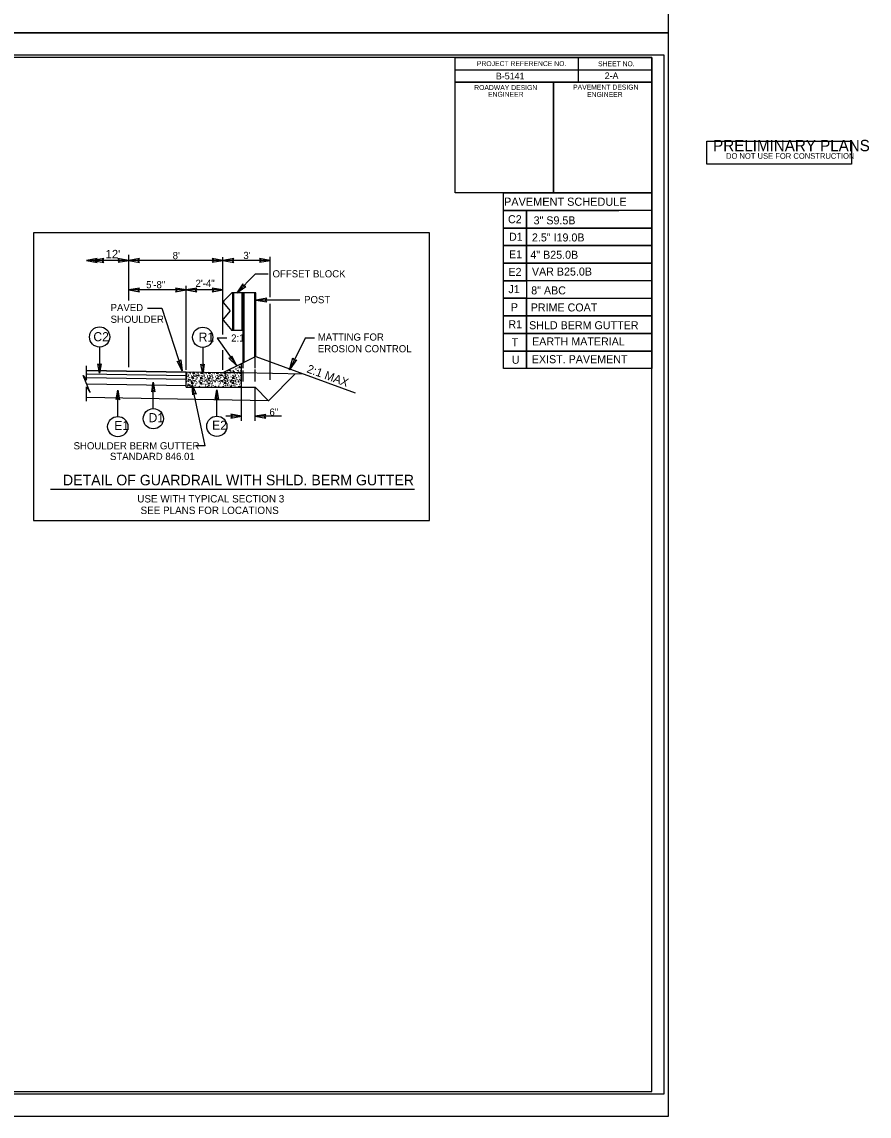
# Model space of a CAD drawing. Extents: x 9470 to 10081, y 10104 to 10463.
# Drawn here: x 9960.6 to 10081.1, y 10104 to 10259.6 of the extents above; entities that cross this region are included whole.
import ezdxf

# ---------------------------------------------------------------- set-up
doc = ezdxf.new("R2010")
doc.units = 0
for name, color, linetype in [('Old_Level_1', 7, 'Continuous'), ('Old_Level_11', 7, 'Continuous'), ('Old_Level_2', 7, 'Continuous'), ('Old_Level_21', 7, 'Continuous'), ('Old_Level_3', 7, 'Continuous'), ('Sheet Cutting Line CELL', 7, 'Continuous'), ('Sheet Data Field CELL', 7, 'Continuous'), ('Sheet Plot Border Inside CELL', 7, 'Continuous'), ('Sheet Plot Border Outside CELL', 7, 'Continuous'), ('Sheet Sticker Preliminary CELL', 7, 'Continuous'), ('Sheet Typical CELL', 7, 'Continuous'), ('Typical ID Circle CELL', 7, 'Continuous'), ('Typical Terminator CELL', 7, 'Continuous'), ('Typical Text ID Circle CELL', 7, 'Continuous')]:
    doc.layers.add(name, color=color, linetype=linetype)

msp = doc.modelspace()

# ---------------------------------------------------------------- linework, layer by layer
at = {"layer": 'Old_Level_1'}
for p, q in [((10050.22, 10235.23), (10050.22, 10210.27)), ((10050.22, 10232.75), (10050.22, 10230.25)), ((9975.8, 10219.94), (9975.8, 10226.43)), ((9989.19, 10215.13), (9989.19, 10226.11)), ((9995.92, 10220.42), (9995.92, 10226.15)), ((9975.8, 10225.63), (9969.78, 10225.63)), ((9989.19, 10225.63), (9975.8, 10225.63)), ((9995.92, 10225.63), (9989.19, 10225.63)), ((9993.79, 10223.68), (9991.15, 10221.03)), ((9995.61, 10223.68), (9993.79, 10223.68)), ((9983.96, 10221.45), (9975.8, 10221.45)), ((9983.96, 10210.08), (9983.96, 10222.01)), ((9989.19, 10221.45), (9983.96, 10221.45)), ((9989.29, 10219.63), (9990.18, 10218.54)), ((9989.3, 10219.9), (9990.46, 10221.03)), ((9993.89, 10221.03), (9990.46, 10221.03)), ((9990.58, 10215.68), (9990.58, 10221.03)), ((9990.73, 10215.68), (9990.73, 10221.03)), ((9991.91, 10215.68), (9991.91, 10221.03)), ((9992.07, 10211.08), (9992.07, 10221.03)), ((9992.22, 10211.15), (9992.22, 10221.03)), ((9993.74, 10211.89), (9993.74, 10221.03)), ((9993.89, 10211.97), (9993.89, 10221.03)), ((10000.15, 10220.01), (9993.89, 10220.01)), ((9995.92, 10208.68), (9995.92, 10219.49)), ((9978.48, 10218.86), (9980.51, 10218.86)), ((9980.51, 10218.86), (9983.4, 10209.96)), ((9990.19, 10218.44), (9989.27, 10217.32)), ((9989.27, 10217.08), (9990.46, 10215.68)), ((9975.8, 10210.48), (9975.8, 10216.22)), ((9992.07, 10215.68), (9990.46, 10215.68)), ((9989.75, 10214.57), (9988.37, 10214.57)), ((9988.37, 10214.57), (9991.15, 10210.64)), ((10002.24, 10214.6), (10000.9, 10214.6)), ((9989.19, 10210.08), (9989.19, 10212.87)), ((9993.89, 10211.97), (9992.07, 10211.08)), ((9993.76, 10210.3), (9993.76, 10211.79)), ((9993.89, 10211.97), (10008, 10206.81)), ((9993.89, 10211.95), (9993.89, 10211.97)), ((9992.07, 10211.08), (9989.19, 10209.68)), ((9990.66, 10210.3), (9990.55, 10210.34)), ((9990.69, 10210.41), (9990.66, 10210.3)), ((9991.84, 10207.62), (9991.84, 10210.97)), ((9992.07, 10210.3), (9992.07, 10211.08)), ((9983.95, 10208.69), (9969.77, 10208.93)), ((9983.96, 10209.77), (9969.78, 10210)), ((9983.96, 10209.25), (9969.88, 10209.48)), ((9983.96, 10207.62), (9983.96, 10209.77)), ((9989.19, 10209.68), (9983.96, 10209.77)), ((9984.09, 10209.55), (9983.96, 10209.76)), ((9983.96, 10209.07), (9983.96, 10209.76)), ((9983.96, 10209.58), (9984.09, 10209.55)), ((9984.91, 10209.08), (9984.72, 10208.93)), ((9984.72, 10208.93), (9985.04, 10208.85)), ((9985.04, 10209.75), (9984.87, 10209.63)), ((9984.87, 10209.63), (9985.2, 10209.55)), ((9985.04, 10208.85), (9984.91, 10209.08)), ((9985.2, 10209.55), (9985.08, 10209.75)), ((9986.16, 10209.03), (9985.96, 10208.88)), ((9985.96, 10208.88), (9986.28, 10208.8)), ((9986.13, 10209.73), (9985.99, 10209.63)), ((9985.99, 10209.63), (9986.31, 10209.55)), ((9986.28, 10208.8), (9986.16, 10209.03)), ((9986.31, 10209.55), (9986.21, 10209.73)), ((9987.22, 10209.71), (9987.1, 10209.63)), ((9987.1, 10209.63), (9987.42, 10209.55)), ((9987.42, 10209.55), (9987.33, 10209.71)), ((9988.3, 10209.69), (9988.22, 10209.63)), ((9988.22, 10209.63), (9988.54, 10209.55)), ((9988.54, 10209.55), (9988.46, 10209.69)), ((9991.84, 10209.64), (9989.19, 10209.68)), ((9989.53, 10209.77), (9989.33, 10209.63)), ((9989.33, 10209.63), (9989.65, 10209.55)), ((9989.59, 10209.05), (9989.39, 10208.91)), ((9989.39, 10208.91), (9989.72, 10208.83)), ((9989.65, 10209.55), (9989.53, 10209.77)), ((9989.72, 10208.83), (9989.59, 10209.05)), ((9990.71, 10209.06), (9990.51, 10208.92)), ((9990.51, 10208.92), (9990.83, 10208.85)), ((9990.77, 10209.84), (9990.57, 10209.69)), ((9990.57, 10209.69), (9990.89, 10209.61)), ((9990.83, 10208.85), (9990.71, 10209.06)), ((9990.89, 10209.61), (9990.77, 10209.84)), ((9991.76, 10209.77), (9991.55, 10209.63)), ((9991.55, 10209.63), (9991.84, 10209.56)), ((9991.84, 10209.63), (9991.76, 10209.77)), ((10000.67, 10209.49), (9991.84, 10209.64)), ((9992.07, 10208.42), (9992.07, 10210)), ((9993.76, 10208.41), (9993.76, 10210.12)), ((9995.67, 10205.7), (9999.48, 10209.51)), ((9983.96, 10207.83), (9969.87, 10208.06)), ((9983.96, 10207.62), (9991.84, 10207.62)), ((9984.87, 10208.34), (9984.67, 10208.2)), ((9984.67, 10208.2), (9984.99, 10208.12)), ((9986.68, 10199.28), (9984.83, 10207.94)), ((9984.99, 10208.12), (9984.87, 10208.34)), ((9986.11, 10208.29), (9985.91, 10208.15)), ((9985.91, 10208.15), (9986.23, 10208.07)), ((9986.23, 10208.07), (9986.11, 10208.29)), ((9989.55, 10208.32), (9989.35, 10208.18)), ((9989.35, 10208.18), (9989.67, 10208.09)), ((9989.67, 10208.09), (9989.55, 10208.32)), ((9990.66, 10208.33), (9990.46, 10208.19)), ((9990.46, 10208.19), (9990.78, 10208.11)), ((9990.78, 10208.11), (9990.66, 10208.33)), ((9991.84, 10202.83), (9991.84, 10207.62)), ((9991.84, 10207.62), (9993.76, 10207.62)), ((9993.76, 10207.62), (9995.67, 10205.7)), ((9993.76, 10202.83), (9993.76, 10207.62)), ((9995.67, 10205.7), (9969.77, 10206.13)), ((9991.84, 10203.49), (9989.62, 10203.49)), ((9997.5, 10203.49), (9993.76, 10203.49)), ((9986.68, 10199.28), (9985.34, 10199.28))]:
    msp.add_line(p, q, dxfattribs=at)
for points in [[(10050.22, 10232.75), (10029.09, 10232.75), (10029.09, 10235.23), (10050.22, 10235.23)], [(10050.22, 10230.25), (10032.4, 10230.25), (10032.4, 10232.75), (10045.53, 10232.75)], [(10000.9, 10214.6), (9998.64, 10210.08)], [(9969.77, 10205.64), (9969.77, 10207.69), (9970.3, 10206.87), (9969.29, 10209.28), (9969.77, 10208.64), (9969.78, 10210.65)]]:
    msp.add_lwpolyline(points, dxfattribs=at)
for points in [[(10029.09, 10232.75), (10032.4, 10232.75), (10032.4, 10230.25), (10029.09, 10230.25)], [(9962.25, 10188.65), (10018.59, 10188.65), (10018.59, 10229.57), (9962.25, 10229.57)], [(10029.09, 10230.25), (10032.4, 10230.25), (10032.4, 10227.76), (10029.09, 10227.76)], [(10032.4, 10230.25), (10050.22, 10230.25), (10050.22, 10227.76), (10032.4, 10227.76)], [(10029.09, 10227.76), (10032.4, 10227.76), (10032.4, 10225.26), (10029.09, 10225.26)], [(10032.4, 10227.76), (10050.22, 10227.76), (10050.22, 10225.26), (10032.4, 10225.26)], [(10029.09, 10225.26), (10032.4, 10225.26), (10032.4, 10222.76), (10029.09, 10222.76)], [(10032.4, 10225.26), (10050.22, 10225.26), (10050.22, 10222.76), (10032.4, 10222.76)], [(10029.09, 10222.76), (10032.4, 10222.76), (10032.4, 10220.26), (10029.09, 10220.26)], [(10029.09, 10220.26), (10032.4, 10220.26), (10032.4, 10217.76), (10029.09, 10217.76)], [(10032.4, 10220.26), (10050.22, 10220.26), (10050.22, 10217.76), (10032.4, 10217.76)], [(10029.09, 10217.76), (10032.4, 10217.76), (10032.4, 10215.26), (10029.09, 10215.26)], [(10032.4, 10217.76), (10050.22, 10217.76), (10050.22, 10215.26), (10032.4, 10215.26)], [(10029.09, 10215.26), (10032.4, 10215.26), (10032.4, 10212.76), (10029.09, 10212.76)], [(10032.4, 10215.26), (10050.22, 10215.26), (10050.22, 10212.76), (10032.4, 10212.76)], [(10029.09, 10212.76), (10032.4, 10212.76), (10032.4, 10210.27), (10029.09, 10210.27)], [(10032.4, 10212.76), (10050.22, 10212.76), (10050.22, 10210.27), (10032.4, 10210.27)], [(9991.52, 10210.4), (9991.82, 10210.49), (9991.78, 10210.3)], [(9969.79, 10210), (9983.96, 10209.77), (9983.95, 10208.69), (9969.77, 10208.93)], [(9984.23, 10208.65), (9984.53, 10208.73), (9984.49, 10208.55)], [(9985.48, 10209.3), (9985.78, 10209.38), (9985.75, 10209.2)], [(9987.06, 10208.9), (9987.36, 10208.99), (9987.33, 10208.81)], [(9988.29, 10208.85), (9988.49, 10208.98), (9988.61, 10208.76)], [(9988.77, 10209.3), (9988.97, 10209.43), (9989.09, 10209.21)], [(9988.84, 10208.54), (9989.14, 10208.63), (9989.1, 10208.45)], [(9984.18, 10207.91), (9984.48, 10208), (9984.44, 10207.82)], [(9987.02, 10208.17), (9987.31, 10208.25), (9987.28, 10208.07)]]:
    msp.add_lwpolyline(points, close=True, dxfattribs=at)
for centre in [(9991.06, 10210.21), (9991.07, 10210.51), (9991.31, 10210.35), (9991.57, 10210.57), (9991.75, 10210.83), (9984, 10208.94), (9984.09, 10209.16), (9984.26, 10209.35), (9984.29, 10208.79), (9984.33, 10209.19), (9984.43, 10209.65), (9984.43, 10208.96), (9984.61, 10209.56), (9984.74, 10209.24), (9984.78, 10209.09), (9985, 10209.48), (9985.04, 10209.27), (9985.21, 10209.16), (9985.37, 10209.35), (9985.41, 10208.79), (9985.44, 10209.19), (9985.54, 10209.65), (9985.54, 10208.96), (9985.73, 10209.56), (9985.85, 10209.24), (9985.9, 10209.09), (9986, 10208.74), (9986.15, 10209.27), (9986.32, 10209.16), (9986.49, 10209.35), (9986.52, 10208.79), (9986.55, 10209.19), (9986.65, 10209.65), (9986.65, 10208.96), (9986.83, 10208.75), (9986.84, 10209.56), (9986.97, 10209.24), (9987.01, 10209.09), (9987.11, 10208.74), (9987.27, 10209.27), (9987.44, 10209.16), (9987.6, 10209.35), (9987.64, 10208.79), (9987.67, 10209.19), (9987.77, 10209.65), (9987.77, 10208.96), (9987.96, 10209.56), (9988.08, 10209.24), (9988.12, 10209.09), (9988.23, 10208.74), (9988.38, 10209.27), (9988.55, 10209.16), (9988.72, 10209.35), (9988.75, 10208.79), (9988.78, 10209.19), (9988.88, 10209.65), (9988.88, 10208.96), (9989.07, 10209.56), (9989.19, 10209.24), (9989.24, 10209.09), (9989.34, 10208.74), (9989.5, 10209.27), (9989.53, 10209.41), (9989.66, 10209.16), (9989.81, 10209.92), (9989.83, 10209.35), (9989.87, 10208.79), (9989.87, 10208.6), (9989.9, 10209.19), (9990, 10209.65), (9990, 10208.96), (9990.15, 10209.96), (9990.18, 10208.65), (9990.19, 10209.56), (9990.26, 10210.03), (9990.3, 10209.84), (9990.31, 10209.24), (9990.35, 10209.09), (9990.45, 10208.6), (9990.45, 10208.74), (9990.61, 10209.27), (9990.64, 10210.03), (9990.78, 10209.16), (9990.88, 10210.13), (9990.95, 10209.35), (9990.98, 10208.79), (9991.01, 10209.19), (9991.11, 10209.65), (9991.11, 10208.96), (9991.22, 10208.75), (9991.27, 10209.96), (9991.3, 10209.56), (9991.38, 10210.03), (9991.41, 10209.84), (9991.42, 10209.24), (9991.47, 10209.09), (9991.57, 10208.74), (9991.73, 10209.27), (9991.75, 10208.92), (9991.76, 10210.03), (9984.04, 10208.43), (9984.13, 10207.77), (9984.18, 10208.51), (9984.25, 10208.06), (9984.28, 10208.46), (9984.38, 10208.23), (9984.61, 10207.78), (9984.66, 10208.52), (9984.69, 10208.5), (9984.73, 10208.36), (9984.76, 10207.74), (9984.81, 10208.47), (9984.99, 10208.54), (9985.16, 10208.43), (9985.22, 10207.85), (9985.26, 10208.58), (9985.36, 10208.06), (9985.39, 10208.46), (9985.49, 10208.23), (9985.8, 10208.5), (9985.85, 10208.36), (9985.87, 10207.74), (9985.92, 10208.47), (9985.95, 10208), (9986.1, 10208.54), (9986.19, 10207.81), (9986.24, 10208.55), (9986.27, 10208.43), (9986.47, 10208.06), (9986.51, 10208.46), (9986.61, 10208.23), (9986.68, 10207.81), (9986.73, 10208.54), (9986.78, 10208.01), (9986.92, 10208.5), (9986.96, 10208.36), (9986.99, 10207.74), (9987.04, 10208.47), (9987.06, 10208), (9987.2, 10207.84), (9987.22, 10208.54), (9987.25, 10208.57), (9987.39, 10208.43), (9987.54, 10207.76), (9987.59, 10208.06), (9987.59, 10208.49), (9987.62, 10208.46), (9987.72, 10208.23), (9987.81, 10207.83), (9987.86, 10208.56), (9988.03, 10208.5), (9988.08, 10208.36), (9988.1, 10207.74), (9988.15, 10208.47), (9988.18, 10208), (9988.33, 10208.54), (9988.5, 10208.43), (9988.6, 10207.79), (9988.65, 10208.53), (9988.7, 10208.06), (9988.73, 10208.46), (9988.83, 10208.23), (9989.15, 10208.5), (9989.19, 10208.36), (9989.22, 10207.74), (9989.27, 10208.47), (9989.29, 10208), (9989.45, 10208.54), (9989.53, 10207.83), (9989.58, 10208.56), (9989.62, 10208.43), (9989.82, 10208.06), (9989.82, 10207.87), (9989.85, 10208.46), (9989.95, 10208.23), (9990.13, 10207.92), (9990.26, 10208.5), (9990.3, 10208.36), (9990.33, 10207.74), (9990.38, 10208.47), (9990.4, 10207.87), (9990.41, 10208), (9990.56, 10208.54), (9990.7, 10207.85), (9990.73, 10208.43), (9990.75, 10208.58), (9990.92, 10207.81), (9990.93, 10208.06), (9990.96, 10208.46), (9990.97, 10208.55), (9991.06, 10208.23), (9991.17, 10208.01), (9991.37, 10208.5), (9991.42, 10208.36), (9991.45, 10207.74), (9991.49, 10208.47), (9991.52, 10208), (9991.68, 10208.54), (9991.7, 10208.19), (9991.72, 10207.75), (9991.77, 10208.48)]:
    msp.add_circle(centre, 0.0157, dxfattribs=at)
for centre, radius, start, end in [((9989.44, 10219.76), 0.199, 135.694, 221.3854), ((9990.11, 10218.49), 0.0919, 326.6101, 36.7601), ((9989.43, 10217.21), 0.202, 144.2385, 219.8658), ((9984.88, 10208.74), 0.0157, 351.9822, 186.1383), ((9984.83, 10208), 0.0157, 351.9822, 186.1383)]:
    msp.add_arc(centre, radius, start, end, dxfattribs=at)
at = {"layer": 'Old_Level_3'}
msp.add_line((10016.46, 10193.09), (9964.64, 10193.09), dxfattribs=at)
at = {"layer": 'Sheet Cutting Line CELL'}
for p, q in [((9816.84, 10257.98), (10052.6, 10257.98)), ((10052.6, 10257.98), (9816.84, 10257.98)), ((9816.84, 10103.98), (10052.6, 10103.98))]:
    msp.add_line(p, q, dxfattribs=at)
at = {"layer": 'Sheet Plot Border Inside CELL'}
msp.add_lwpolyline([(10051.97, 10254.84), (9818.66, 10254.84), (9818.66, 10107.13), (10051.97, 10107.13)], close=True, dxfattribs=at)
at = {"layer": 'Sheet Plot Border Outside CELL'}
for points in [[(10052.6, 10411.98), (9816.84, 10411.98), (9816.84, 10257.98), (10052.6, 10257.98)], [(10052.6, 10257.98), (9816.84, 10257.98), (9816.84, 10103.98), (10052.6, 10103.98)]]:
    msp.add_lwpolyline(points, close=True, dxfattribs=at)
at = {"layer": 'Sheet Sticker Preliminary CELL'}
msp.add_lwpolyline([(10058.02, 10239.33), (10058.02, 10242.62), (10078.6, 10242.62), (10078.6, 10239.33)], close=True, dxfattribs=at)
at = {"layer": 'Sheet Typical CELL'}
for p, q in [((10039.72, 10254.48), (10039.72, 10250.98)), ((10022.21, 10252.73), (10050.22, 10252.73)), ((10036.22, 10250.98), (10036.22, 10235.23))]:
    msp.add_line(p, q, dxfattribs=at)
for points in [[(10050.22, 10254.48), (9840.22, 10254.48), (9840.22, 10107.48), (10050.22, 10107.48)], [(10022.21, 10254.48), (10050.22, 10254.48), (10050.22, 10250.98), (10022.21, 10250.98)], [(10022.21, 10250.98), (10036.22, 10250.98), (10036.22, 10235.23), (10022.21, 10235.23)], [(10036.22, 10250.98), (10050.22, 10250.98), (10050.22, 10235.23), (10036.22, 10235.23)]]:
    msp.add_lwpolyline(points, close=True, dxfattribs=at)
at = {"layer": 'Typical ID Circle CELL'}
for p, q in [((9971.65, 10213.32), (9971.65, 10209.59)), ((9986.31, 10213.27), (9986.31, 10209.54)), ((9974.23, 10203.46), (9974.23, 10207.18)), ((9979.29, 10204.58), (9979.29, 10208.31)), ((9988.33, 10203.5), (9988.33, 10207.23))]:
    msp.add_line(p, q, dxfattribs=at)
for centre in [(9971.65, 10214.76), (9986.31, 10214.71), (9979.29, 10203.14), (9974.23, 10202.01), (9988.33, 10202.06)]:
    msp.add_circle(centre, 1.44, dxfattribs=at)
at = {"layer": 'Typical Terminator CELL'}
for points in [[(9971.31, 10225.9), (9969.78, 10225.63), (9971.32, 10225.36), (9971.12, 10225.63)], [(9972.26, 10225.9), (9970.73, 10225.64), (9972.27, 10225.36), (9972.08, 10225.64)], [(9974.27, 10225.37), (9975.8, 10225.63), (9974.26, 10225.91), (9974.46, 10225.63)], [(9977.33, 10225.9), (9975.8, 10225.63), (9977.34, 10225.36), (9977.14, 10225.63)], [(9987.66, 10225.37), (9989.19, 10225.63), (9987.65, 10225.91), (9987.85, 10225.63)], [(9990.72, 10225.9), (9989.19, 10225.63), (9990.73, 10225.36), (9990.53, 10225.63)], [(9994.39, 10225.37), (9995.92, 10225.63), (9994.38, 10225.91), (9994.57, 10225.63)], [(9977.33, 10221.71), (9975.8, 10221.45), (9977.34, 10221.17), (9977.14, 10221.45)], [(9982.43, 10221.18), (9983.96, 10221.45), (9982.42, 10221.72), (9982.62, 10221.45)], [(9985.49, 10221.71), (9983.96, 10221.45), (9985.5, 10221.17), (9985.31, 10221.45)], [(9987.66, 10221.18), (9989.19, 10221.45), (9987.65, 10221.72), (9987.85, 10221.45)], [(9992.04, 10222.3), (9991.15, 10221.03), (9992.43, 10221.93), (9992.1, 10221.98)], [(9995.42, 10220.28), (9993.89, 10220.01), (9995.43, 10219.74), (9995.23, 10220.01)], [(9990.05, 10211.74), (9991.15, 10210.64), (9990.48, 10212.05), (9990.37, 10211.73)], [(9999.68, 10211.5), (9998.64, 10210.08), (9999.15, 10211.78), (9999.32, 10211.45)], [(9971.88, 10210.93), (9971.65, 10209.59), (9971.41, 10210.93), (9971.65, 10210.76)], [(9983.18, 10211.49), (9983.4, 10209.96), (9982.66, 10211.34), (9982.98, 10211.24)], [(9986.54, 10210.88), (9986.31, 10209.54), (9986.07, 10210.88), (9986.31, 10210.71)], [(9974, 10205.85), (9974.23, 10207.18), (9974.47, 10205.84), (9974.23, 10206.01)], [(9979.06, 10206.97), (9979.29, 10208.31), (9979.52, 10206.96), (9979.29, 10207.13)], [(9984.89, 10206.51), (9984.83, 10207.94), (9985.37, 10206.61), (9985.09, 10206.73)], [(9988.1, 10205.89), (9988.33, 10207.23), (9988.57, 10205.88), (9988.33, 10206.05)], [(9990.31, 10203.23), (9991.84, 10203.49), (9990.3, 10203.76), (9990.5, 10203.49)], [(9995.29, 10203.75), (9993.76, 10203.49), (9995.3, 10203.22), (9995.1, 10203.49)]]:
    msp.add_lwpolyline(points, close=True, dxfattribs=at)

# ---------------------------------------------------------------- texts
at = {"layer": 'Old_Level_1'}
for s, height, p in [("8'", 1.02, (9982.04, 10225.82)), ("3'", 1.02, (9992.1, 10225.84)), ('OFFSET BLOCK', 1.0201, (9996.25, 10223.23)), ('5\'-8"', 1.02, (9978.27, 10221.68)), ('2\'-4"', 1.02, (9985.3, 10221.88)), ('POST', 1.02, (10000.74, 10219.56)), ('PAVED', 1.02, (9973.21, 10218.43)), ('SHOULDER', 1.02, (9973.21, 10216.77)), ('2:1', 1.02, (9990.36, 10214.1)), ('MATTING FOR', 1.0201, (10002.69, 10214.24)), ('EROSION CONTROL', 1.0201, (10002.69, 10212.58)), ('6"', 1.02, (9995.81, 10203.57)), ('SHOULDER BERM GUTTER', 1.0201, (9967.95, 10198.78)), ('STANDARD 846.01', 1.0201, (9973.12, 10197.27))]:
    msp.add_text(s, height=height, dxfattribs=at).set_placement(p)
msp.add_text('2:1 MAX', height=1.2, rotation=339.8963, dxfattribs=at).set_placement((10001.02, 10209.76))
at = {"layer": 'Old_Level_11'}
for s, height, p in [('DETAIL OF GUARDRAIL WITH SHLD. BERM GUTTER', 1.5, (9966.44, 10193.67)), ('USE WITH TYPICAL SECTION 3', 1.05, (9977.01, 10191.23)), ('SEE PLANS FOR LOCATIONS', 1.05, (9977.47, 10189.59))]:
    msp.add_text(s, height=height, dxfattribs=at).set_placement(p)
at = {"layer": 'Old_Level_2'}
msp.add_text("12'", height=1.2, dxfattribs=at).set_placement((9972.5, 10225.94))
at = {"layer": 'Old_Level_21'}
for s, height, p in [(' PAVEMENT SCHEDULE', 1.1616, (10028.75, 10233.41)), ('C2', 1.138, (10029.75, 10230.93)), ('3" S9.5B', 1.138, (10033.39, 10230.77)), ('D1', 1.138, (10029.89, 10228.44)), ('2.5" I19.0B', 1.1384, (10033.15, 10228.34)), ('E1', 1.138, (10029.89, 10225.94)), ('4" B25.0B', 1.138, (10032.93, 10225.88)), ('E2', 1.138, (10029.81, 10223.44)), ('VAR B25.0B', 1.138, (10033.15, 10223.49)), ('J1', 1.138, (10029.81, 10220.99)), ('8" ABC', 1.138, (10033.05, 10220.81)), ('P', 1.14, (10030.15, 10218.42)), ('PRIME COAT', 1.138, (10032.98, 10218.39)), ('R1', 1.138, (10029.8, 10216)), ('SHLD BERM GUTTER', 1.1384, (10032.75, 10215.86)), ('T', 1.14, (10030.27, 10213.44)), ('EARTH MATERIAL', 1.1384, (10033.17, 10213.55)), ('U', 1.14, (10030.29, 10210.95)), ('EXIST. PAVEMENT', 1.1384, (10033.13, 10211.03))]:
    msp.add_text(s, height=height, dxfattribs=at).set_placement(p)
at = {"layer": 'Sheet Data Field CELL'}
for s, p in [('B-5141   ', (10028.02, 10251.38)), ('2-A', (10043.5, 10251.42))]:
    msp.add_text(s, height=0.945, dxfattribs=at).set_placement(p)
at = {"layer": 'Sheet Sticker Preliminary CELL'}
for s, height, p in [('PRELIMINARY PLANS', 1.6128, (10058.93, 10241.17)), ('DO NOT USE FOR CONSTRUCTION', 0.8064, (10060.76, 10240.09))]:
    msp.add_text(s, height=height, dxfattribs=at).set_placement(p)
at = {"layer": 'Sheet Typical CELL'}
for s, p in [('PROJECT REFERENCE NO.', (10025.32, 10253.27)), ('SHEET NO.', (10042.56, 10253.25)), ('PAVEMENT DESIGN', (10039.01, 10249.93)), ('ROADWAY DESIGN', (10024.94, 10249.87)), ('ENGINEER', (10026.91, 10248.91)), ('ENGINEER', (10041, 10248.89))]:
    msp.add_text(s, height=0.7, dxfattribs=at).set_placement(p)
at = {"layer": 'Typical Text ID Circle CELL'}
for s, p in [('C2', (9970.76, 10214.15)), ('R1', (9985.74, 10214.1)), ('E1', (9973.73, 10201.52)), ('D1', (9978.61, 10202.64)), ('E2', (9987.65, 10201.56))]:
    msp.add_text(s, height=1.291, dxfattribs=at).set_placement(p)

doc.saveas('drawing.dxf')
